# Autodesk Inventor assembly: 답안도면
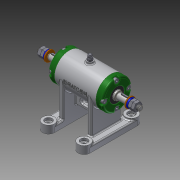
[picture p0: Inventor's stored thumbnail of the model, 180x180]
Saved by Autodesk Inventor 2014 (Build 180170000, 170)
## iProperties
Created: 2015-11
Part Number: 답안도면
Document SubType Name: Assembly
Designer: 702
Author: 702
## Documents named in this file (16)
- C:\Users\702\Desktop\451109V1010\답안도면.iam
- C:\Users\702\Desktop\451109V1010\본체.ipt
- C:\Users\702\Desktop\451109V1010\V벨트풀리.ipt
- C:\Users\702\Desktop\451109V1010\너트 M 8.ipt
- C:\Users\702\Desktop\451109V1010\니플 M 6 x 0.75.ipt
- C:\Users\702\Desktop\451109V1010\베어링 15 x 32 x 9.ipt
- C:\Users\702\Desktop\451109V1010\볼트 M 6 x 8.ipt
- C:\Users\702\Desktop\451109V1010\볼트 M4 x 12.ipt
- C:\Users\702\Desktop\451109V1010\스퍼기어.ipt
- C:\Users\702\Desktop\451109V1010\스프링와셔 8.ipt
- C:\Users\702\Desktop\451109V1010\오일 실 15 25 7.ipt
- C:\Users\702\Desktop\451109V1010\와셔 6x11.5.ipt
- C:\Users\702\Desktop\451109V1010\와셔 8x17.ipt
- C:\Users\702\Desktop\451109V1010\축.ipt
- C:\Users\702\Desktop\451109V1010\커버.ipt
- C:\Users\702\Desktop\451109V1010\키 3 x 3 x 12.ipt
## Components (11 placed, 3 different names)
1. V벨트풀리:1
2. KS B 2023 6002 - 15 x 32 x 9:1
3. KS B 2023 6002 - 15 x 32 x 9:2
4. ISO 4762 M4 x 12:2
5. ISO 4762 M4 x 12:3
6. ISO 4762 M4 x 12:4
7. ISO 4762 M4 x 12:5
8. ISO 4762 M4 x 12:1
9. ISO 4762 M4 x 12:6
10. ISO 4762 M4 x 12:7
11. ISO 4762 M4 x 12:8
